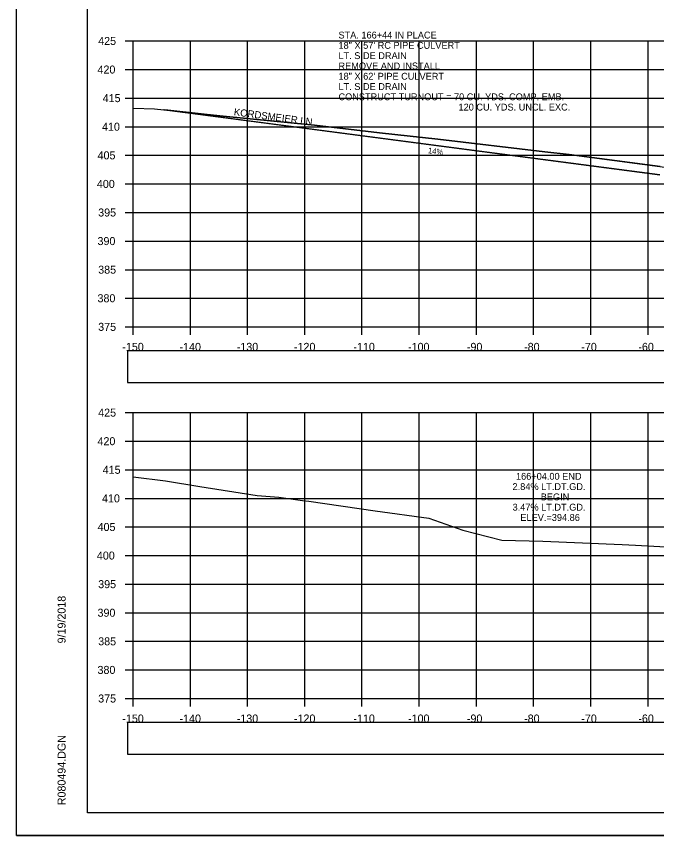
# Model space of a CAD drawing. Extents: x 1376273 to 1384221, y 378927 to 384592.
# Drawn here: x 1378054 to 1378166, y 380751.8 to 380895.1 of the extents above; entities that cross this region are included whole.
import ezdxf

# ---------------------------------------------------------------- set-up
doc = ezdxf.new("R2010")
doc.units = 0
for name, color, linetype in [('R_Axis', 7, 'Continuous'), ('R_Axis Annot', 7, 'Continuous'), ('R_Border', 7, 'Continuous'), ('R_Drive', 7, 'Continuous'), ('R_Exist Surface', 7, 'Continuous'), ('R_Grid', 7, 'Continuous'), ('R_No Plot', 7, 'Continuous'), ('R_Xsect Elev', 7, 'Continuous'), ('T_Notes', 7, 'Continuous')]:
    doc.layers.add(name, color=color, linetype=linetype)

msp = doc.modelspace()

# ---------------------------------------------------------------- linework, layer by layer
at = {"layer": 'R_Axis'}
for p, q in [((1378073.06, 380890.83), (1378074.46, 380890.83)), ((1378074.46, 380840.83), (1378074.46, 380890.83)), ((1378073.06, 380885.83), (1378074.46, 380885.83)), ((1378073.06, 380880.83), (1378074.46, 380880.83)), ((1378073.06, 380875.83), (1378074.46, 380875.83)), ((1378073.06, 380870.83), (1378074.46, 380870.83)), ((1378073.06, 380865.83), (1378074.46, 380865.83)), ((1378073.06, 380860.83), (1378074.46, 380860.83)), ((1378073.06, 380855.83), (1378074.46, 380855.83)), ((1378073.06, 380850.83), (1378074.46, 380850.83)), ((1378073.06, 380845.83), (1378074.46, 380845.83)), ((1378073.06, 380840.83), (1378074.46, 380840.83)), ((1378074.46, 380840.83), (1378374.46, 380840.83)), ((1378074.46, 380839.43), (1378074.46, 380840.83)), ((1378084.46, 380839.43), (1378084.46, 380840.83)), ((1378094.46, 380839.43), (1378094.46, 380840.83)), ((1378104.46, 380839.43), (1378104.46, 380840.83)), ((1378114.46, 380839.43), (1378114.46, 380840.83)), ((1378124.46, 380839.43), (1378124.46, 380840.83)), ((1378134.46, 380839.43), (1378134.46, 380840.83)), ((1378144.46, 380839.43), (1378144.46, 380840.83)), ((1378154.46, 380839.43), (1378154.46, 380840.83)), ((1378164.46, 380839.43), (1378164.46, 380840.83)), ((1378073.06, 380825.83), (1378074.46, 380825.83)), ((1378074.46, 380775.83), (1378074.46, 380825.83)), ((1378073.06, 380820.83), (1378074.46, 380820.83)), ((1378073.06, 380815.83), (1378074.46, 380815.83)), ((1378073.06, 380810.83), (1378074.46, 380810.83)), ((1378073.06, 380805.83), (1378074.46, 380805.83)), ((1378073.06, 380800.83), (1378074.46, 380800.83)), ((1378073.06, 380795.83), (1378074.46, 380795.83)), ((1378073.06, 380790.83), (1378074.46, 380790.83)), ((1378073.06, 380785.83), (1378074.46, 380785.83)), ((1378073.06, 380780.83), (1378074.46, 380780.83)), ((1378073.06, 380775.83), (1378074.46, 380775.83)), ((1378074.46, 380775.83), (1378374.46, 380775.83)), ((1378074.46, 380774.43), (1378074.46, 380775.83)), ((1378084.46, 380774.43), (1378084.46, 380775.83)), ((1378094.46, 380774.43), (1378094.46, 380775.83)), ((1378104.46, 380774.43), (1378104.46, 380775.83)), ((1378114.46, 380774.43), (1378114.46, 380775.83)), ((1378124.46, 380774.43), (1378124.46, 380775.83)), ((1378134.46, 380774.43), (1378134.46, 380775.83)), ((1378144.46, 380774.43), (1378144.46, 380775.83)), ((1378154.46, 380774.43), (1378154.46, 380775.83)), ((1378164.46, 380774.43), (1378164.46, 380775.83))]:
    msp.add_line(p, q, dxfattribs=at)
at = {"layer": 'R_Axis Annot'}
for points in [[(1378073.48, 380831.09), (1378375.28, 380831.09), (1378375.28, 380836.61), (1378073.48, 380836.61)], [(1378073.48, 380766.08), (1378375.28, 380766.08), (1378375.28, 380771.61), (1378073.48, 380771.61)]]:
    msp.add_lwpolyline(points, close=True, dxfattribs=at)
at = {"layer": 'R_Border'}
for p, q in [((1378066.46, 380755.83), (1378066.46, 380961.29)), ((1378066.46, 380755.83), (1378066.46, 380755.83)), ((1378382.64, 380755.83), (1378066.46, 380755.83))]:
    msp.add_line(p, q, dxfattribs=at)
at = {"layer": 'R_Drive'}
msp.add_line((1378166.52, 380867.39), (1378079.83, 380878.8), dxfattribs=at)
at = {"layer": 'R_Exist Surface'}
for points in [[(1378074.46, 380879.1), (1378074.52, 380879.1), (1378078.18, 380878.98), (1378086.9, 380878.02), (1378090.19, 380877.7), (1378106.16, 380876.1), (1378117.51, 380874.79), (1378127.7, 380873.63), (1378146.43, 380871.45), (1378150.68, 380870.97), (1378167.38, 380868.75)], [(1378074.46, 380814.58), (1378080.11, 380813.87), (1378086.12, 380812.88), (1378096.15, 380811.35), (1378099.91, 380811.05), (1378104.05, 380810.44), (1378105.19, 380810.32), (1378116.77, 380808.66), (1378126.15, 380807.36), (1378132.06, 380805.27), (1378138.89, 380803.53), (1378146.06, 380803.32), (1378159.92, 380802.78), (1378162.28, 380802.64), (1378177.19, 380801.85)]]:
    msp.add_lwpolyline(points, dxfattribs=at)
at = {"layer": 'R_Grid'}
for p, q in [((1378074.46, 380890.83), (1378374.46, 380890.83)), ((1378074.46, 380840.83), (1378074.46, 380890.83)), ((1378084.46, 380840.83), (1378084.46, 380890.83)), ((1378094.46, 380840.83), (1378094.46, 380890.83)), ((1378104.46, 380840.83), (1378104.46, 380890.83)), ((1378114.46, 380840.83), (1378114.46, 380890.83)), ((1378124.46, 380840.83), (1378124.46, 380890.83)), ((1378134.46, 380840.83), (1378134.46, 380890.83)), ((1378144.46, 380840.83), (1378144.46, 380890.83)), ((1378154.46, 380840.83), (1378154.46, 380890.83)), ((1378164.46, 380840.83), (1378164.46, 380890.83)), ((1378074.46, 380885.83), (1378374.46, 380885.83)), ((1378074.46, 380880.83), (1378374.46, 380880.83)), ((1378074.46, 380875.83), (1378374.46, 380875.83)), ((1378074.46, 380870.83), (1378374.46, 380870.83)), ((1378074.46, 380865.83), (1378374.46, 380865.83)), ((1378074.46, 380860.83), (1378374.46, 380860.83)), ((1378074.46, 380855.83), (1378374.46, 380855.83)), ((1378074.46, 380850.83), (1378374.46, 380850.83)), ((1378074.46, 380845.83), (1378374.46, 380845.83)), ((1378074.46, 380840.83), (1378374.46, 380840.83)), ((1378074.46, 380825.83), (1378374.46, 380825.83)), ((1378074.46, 380775.83), (1378074.46, 380825.83)), ((1378084.46, 380775.83), (1378084.46, 380825.83)), ((1378094.46, 380775.83), (1378094.46, 380825.83)), ((1378104.46, 380775.83), (1378104.46, 380825.83)), ((1378114.46, 380775.83), (1378114.46, 380825.83)), ((1378124.46, 380775.83), (1378124.46, 380825.83)), ((1378134.46, 380775.83), (1378134.46, 380825.83)), ((1378144.46, 380775.83), (1378144.46, 380825.83)), ((1378154.46, 380775.83), (1378154.46, 380825.83)), ((1378164.46, 380775.83), (1378164.46, 380825.83)), ((1378074.46, 380820.83), (1378374.46, 380820.83)), ((1378074.46, 380815.83), (1378374.46, 380815.83)), ((1378074.46, 380810.83), (1378374.46, 380810.83)), ((1378074.46, 380805.83), (1378374.46, 380805.83)), ((1378074.46, 380800.83), (1378374.46, 380800.83)), ((1378074.46, 380795.83), (1378374.46, 380795.83)), ((1378074.46, 380790.83), (1378374.46, 380790.83)), ((1378074.46, 380785.83), (1378374.46, 380785.83)), ((1378074.46, 380780.83), (1378374.46, 380780.83)), ((1378074.46, 380775.83), (1378374.46, 380775.83))]:
    msp.add_line(p, q, dxfattribs=at)
at = {"layer": 'R_No Plot'}
msp.add_line((1378054.06, 380751.85), (1378387.39, 380751.85), dxfattribs=at)
for points in [[(1378054.05, 380965.19), (1378387.39, 380965.19), (1378387.39, 380751.85), (1378054.05, 380751.85)], [(1378300.38, 380961.29), (1378300.38, 380951.41), (1378336.11, 380951.41), (1378336.11, 380948.49), (1378359.31, 380948.49), (1378359.31, 380924.16), (1378382.64, 380924.16), (1378382.64, 380755.83), (1378066.46, 380755.83), (1378066.46, 380961.29)]]:
    msp.add_lwpolyline(points, close=True, dxfattribs=at)
at = {"layer": 'T_Notes'}
msp.add_line((1378080.02, 380878.77), (1378166.52, 380867.39), dxfattribs=at)
msp.add_lwpolyline([(1378166.6, 380868.85), (1378150.68, 380870.97), (1378146.43, 380871.45), (1378127.7, 380873.63), (1378117.51, 380874.79), (1378106.16, 380876.1), (1378090.19, 380877.7), (1378086.9, 380878.02), (1378080.02, 380878.77)], dxfattribs=at)

# ---------------------------------------------------------------- texts
at = {"layer": 'R_Axis Annot'}
for s, height, p in [('STA. 166+44 IN PLACE', 1.2, (1378110.35, 380891.26)), ('425', 1.4, (1378068.35, 380890.13)), ('18" X 57\' RC PIPE CULVERT', 1.2, (1378110.35, 380889.46)), ('LT. SIDE DRAIN', 1.2, (1378110.35, 380887.66)), ('420', 1.4, (1378068.23, 380885.13)), ('REMOVE AND INSTALL', 1.2, (1378110.35, 380885.86)), ('18" X 62\' PIPE CULVERT', 1.2, (1378110.35, 380884.06)), ('LT. SIDE DRAIN', 1.2, (1378110.35, 380882.26)), ('415', 1.4, (1378069.14, 380880.13)), ('CONSTRUCT TURNOUT = 70 CU. YDS. COMP. EMB.', 1.2, (1378110.35, 380880.46)), ('    120 CU. YDS. UNCL. EXC.', 1.2, (1378129.55, 380878.66)), ('410', 1.4, (1378069.02, 380875.13)), ('405', 1.4, (1378068.24, 380870.13)), ('400', 1.4, (1378068.12, 380865.13)), ('395', 1.4, (1378068.35, 380860.13)), ('390', 1.4, (1378068.23, 380855.13)), ('385', 1.4, (1378068.35, 380850.13)), ('380', 1.4, (1378068.23, 380845.13)), ('375', 1.4, (1378068.35, 380840.13)), ('-150', 1.4, (1378072.57, 380836.63)), ('-140', 1.4, (1378082.57, 380836.63)), ('-130', 1.4, (1378092.57, 380836.63)), ('-120', 1.4, (1378102.57, 380836.63)), ('-110', 1.4, (1378112.96, 380836.63)), ('-100', 1.4, (1378122.51, 380836.63)), ('-90', 1.4, (1378132.8, 380836.63)), ('-80', 1.4, (1378142.8, 380836.63)), ('-70', 1.4, (1378152.8, 380836.63)), ('-60', 1.4, (1378162.77, 380836.63)), ('425', 1.4, (1378068.35, 380825.13)), ('420', 1.4, (1378068.23, 380820.13)), ('415', 1.4, (1378069.14, 380815.13)), ('410', 1.4, (1378069.02, 380810.13)), ('405', 1.4, (1378068.24, 380805.13)), ('400', 1.4, (1378068.12, 380800.13)), ('395', 1.4, (1378068.35, 380795.13)), ('390', 1.4, (1378068.23, 380790.13)), ('385', 1.4, (1378068.35, 380785.13)), ('380', 1.4, (1378068.23, 380780.13)), ('375', 1.4, (1378068.35, 380775.13)), ('-150', 1.4, (1378072.57, 380771.63)), ('-140', 1.4, (1378082.57, 380771.63)), ('-130', 1.4, (1378092.57, 380771.63)), ('-120', 1.4, (1378102.57, 380771.63)), ('-110', 1.4, (1378112.96, 380771.63)), ('-100', 1.4, (1378122.51, 380771.63)), ('-90', 1.4, (1378132.8, 380771.63)), ('-80', 1.4, (1378142.8, 380771.63)), ('-70', 1.4, (1378152.8, 380771.63)), ('-60', 1.4, (1378162.77, 380771.63))]:
    msp.add_text(s, height=height, dxfattribs=at).set_placement(p)
at = {"layer": 'R_Border'}
for s, p in [('9/19/2018', (1378062.65, 380785.47)), ('R080494.DGN', (1378062.65, 380757.16))]:
    msp.add_text(s, height=1.4, rotation=90, dxfattribs=at).set_placement(p)
at = {"layer": 'R_Drive'}
for s, height, p in [('KORDSMEIER LN.', 1.25, (1378092, 380877.84)), ('14%', 1, (1378125.94, 380871.2))]:
    msp.add_text(s, height=height, rotation=352.505, dxfattribs=at).set_placement(p)
at = {"layer": 'R_Xsect Elev'}
for s, p in [('166+04.00 END', (1378141.38, 380814.09)), ('2.84% LT.DT.GD.', (1378140.78, 380812.29)), ('BEGIN', (1378145.71, 380810.49)), ('3.47% LT.DT.GD.', (1378140.78, 380808.69)), ('ELEV.=394.86', (1378142.15, 380806.89))]:
    msp.add_text(s, height=1.2, rotation=360, dxfattribs=at).set_placement(p)

doc.saveas('drawing.dxf')
